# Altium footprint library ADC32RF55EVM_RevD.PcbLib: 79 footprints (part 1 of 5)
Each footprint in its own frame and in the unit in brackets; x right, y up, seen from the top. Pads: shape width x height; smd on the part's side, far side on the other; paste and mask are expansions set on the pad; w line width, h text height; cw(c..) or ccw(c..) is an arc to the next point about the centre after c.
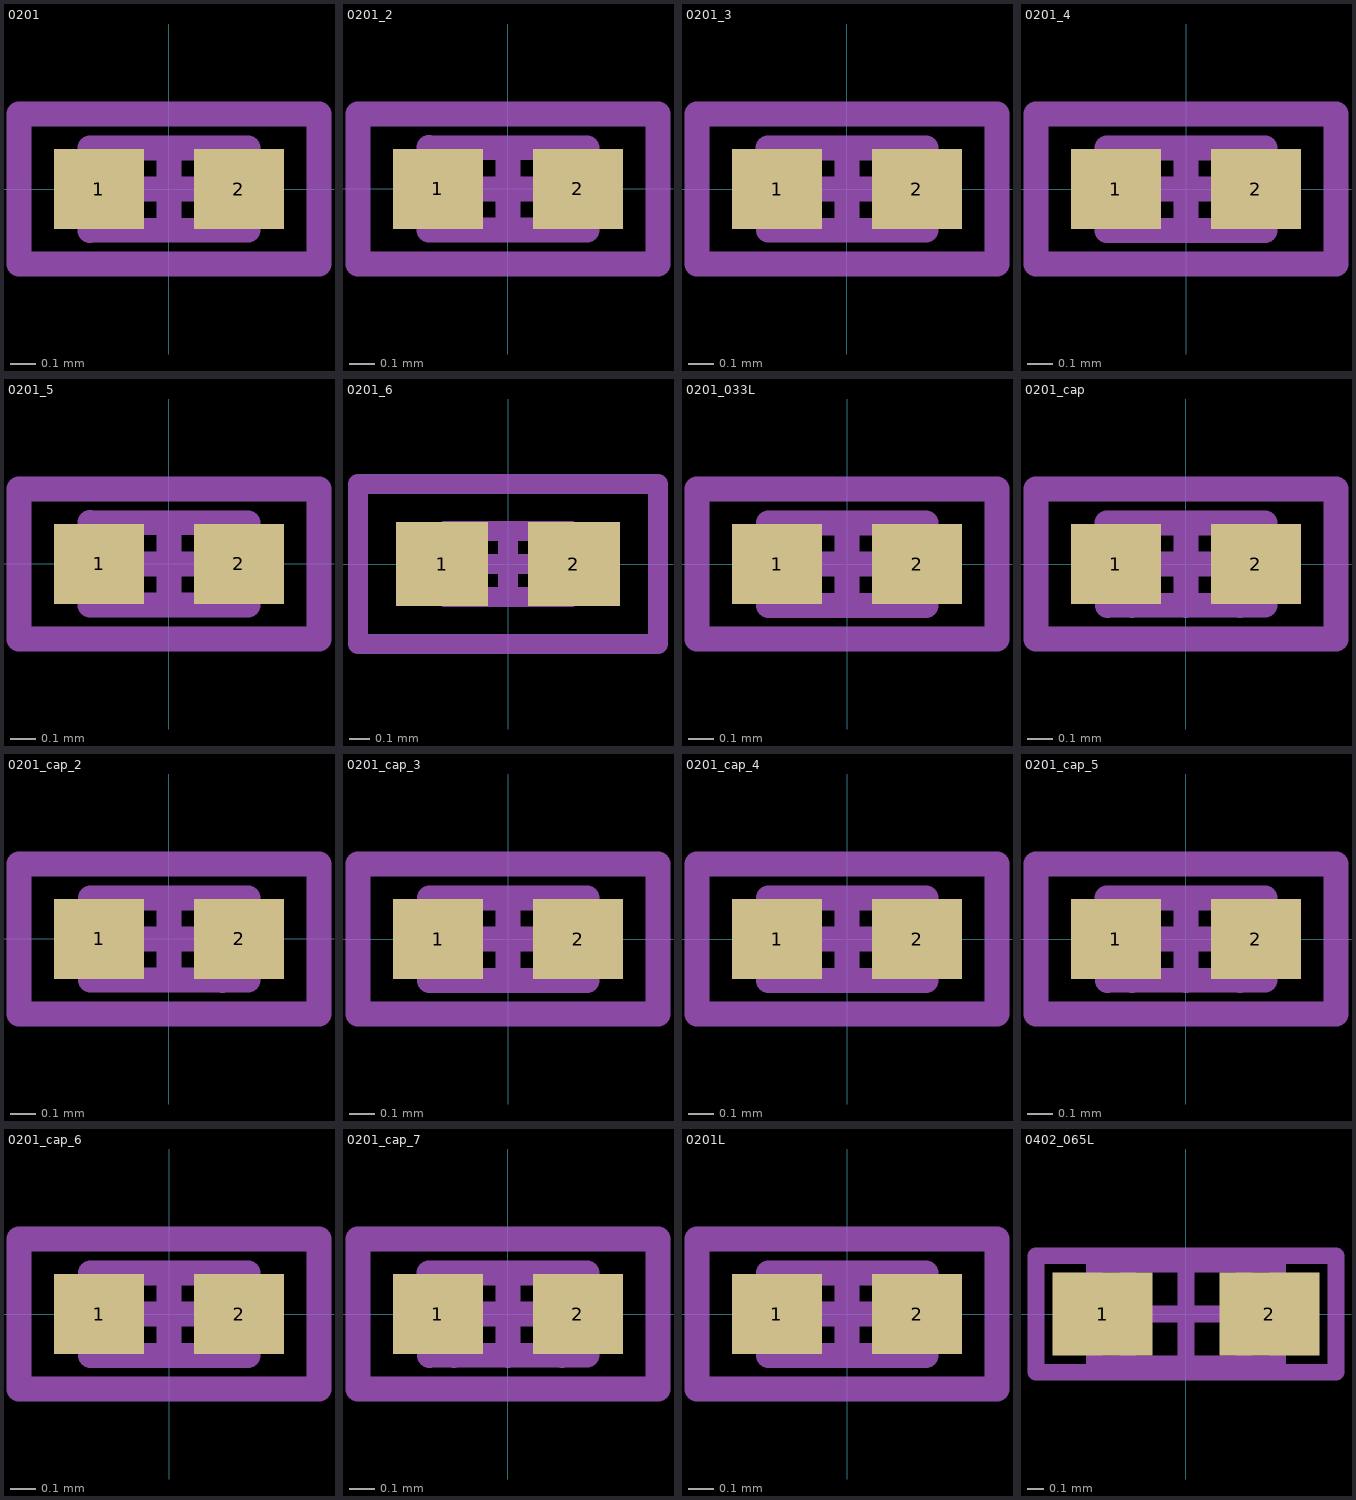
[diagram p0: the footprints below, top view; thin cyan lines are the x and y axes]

## 0201 [mm] "Data from Kemet datasheet CC101_COM dated 7/28/11"
height 0.26
pads (2):
  rect 0.36x0.32 smd mask+0.048: 1(-0.28,0) 2(0.28,0)
Mechanical 5:
  lines w0.1: -0.6,-0.3 0.6,-0.3 0.6,0.3 -0.6,0.3 -0.6,-0.3
  text ".Designator" at -0.254,0 h0.64
Mechanical 13:
  lines w0.1: -0.215,-0.165 -0.215,0.165 ; 0.215,-0.165 0.215,0.165 ; -0.315,-0.165 -0.315,0.165 0.315,0.165 0.315,-0.165 -0.315,-0.165
Mechanical 15:
  lines w0.1: -0.165,0 0.165,0 ; 0,-0.165 0,0.165 ; -0.6,-0.3 -0.6,0.3 0.6,0.3 0.6,-0.3 -0.6,-0.3
3D body: height 0.26, standoff 0, extent -0.314,-0.164 -0.216,0.164
3D body: height 0.26, standoff 0, extent -0.214,-0.164 0.214,0.164
3D body: height 0.26, standoff 0, extent 0.216,-0.164 0.315,0.164

## 0201_2 [mm]
pads (2):
  rect 0.36x0.32 smd mask+0.048: 1(-0.28,0) 2(0.28,0)
Mechanical 5:
  lines w0.1: -0.6,-0.3 -0.6,0.3 0.6,0.3 0.6,-0.3 -0.6,-0.3
  text ".Designator" at -0.254,0 h0.64
Mechanical 13:
  lines w0.1: -0.215,-0.165 -0.215,0.165 ; 0.215,-0.165 0.215,0.165 ; -0.315,-0.165 0.315,-0.165 0.315,0.165 -0.315,0.165 -0.315,-0.165
Mechanical 15:
  lines w0.1: -0.165,0 0.165,0 ; 0,-0.165 0,0.165 ; -0.6,-0.3 0.6,-0.3 0.6,0.3 -0.6,0.3 -0.6,-0.3
3D body: height 0.26, standoff 0, extent 0.216,-0.164 0.314,0.164
3D body: height 0.26, standoff 0, extent -0.214,-0.164 0.214,0.164
3D body: height 0.26, standoff 0, extent -0.314,-0.164 -0.216,0.164

## 0201_3 [mm]
pads (2):
  rect 0.36x0.32 smd mask+0.048: 1(-0.28,0) 2(0.28,0)
Mechanical 5:
  lines w0.1: -0.6,-0.3 0.6,-0.3 0.6,0.3 -0.6,0.3 -0.6,-0.3
  text ".Designator" at -0.254,0 h0.64
Mechanical 13:
  lines w0.1: -0.215,-0.165 -0.215,0.165 ; 0.215,-0.165 0.215,0.165 ; -0.315,-0.165 -0.315,0.165 0.315,0.165 0.315,-0.165 -0.315,-0.165
Mechanical 15:
  lines w0.1: -0.165,0 0.165,0 ; 0,-0.165 0,0.165 ; -0.6,-0.3 -0.6,0.3 0.6,0.3 0.6,-0.3 -0.6,-0.3
3D body: height 0.26, standoff 0, extent -0.314,-0.164 -0.216,0.164
3D body: height 0.26, standoff 0, extent -0.214,-0.164 0.214,0.164
3D body: height 0.26, standoff 0, extent 0.216,-0.164 0.314,0.164

## 0201_4 [mm]
pads (2):
  rect 0.36x0.32 smd mask+0.048: 1(-0.28,0) 2(0.28,0)
Mechanical 5:
  lines w0.1: -0.6,-0.3 0.6,-0.3 0.6,0.3 -0.6,0.3 -0.6,-0.3
  text ".Designator" at -0.254,0 h0.64
Mechanical 13:
  lines w0.1: -0.215,-0.165 -0.215,0.165 ; 0.215,-0.165 0.215,0.165 ; -0.315,-0.165 -0.315,0.165 0.315,0.165 0.315,-0.165 -0.315,-0.165
Mechanical 15:
  lines w0.1: -0.165,0 0.165,0 ; 0,-0.165 0,0.165 ; -0.6,-0.3 -0.6,0.3 0.6,0.3 0.6,-0.3 -0.6,-0.3
3D body: height 0.26, standoff 0, extent -0.314,-0.164 -0.216,0.164
3D body: height 0.26, standoff 0, extent -0.214,-0.164 0.214,0.164
3D body: height 0.26, standoff 0, extent 0.216,-0.164 0.314,0.164

## 0201_5 [mm]
pads (2):
  rect 0.36x0.32 smd mask+0.048: 1(-0.28,0) 2(0.28,0)
Mechanical 5:
  lines w0.1: -0.6,-0.3 0.6,-0.3 0.6,0.3 -0.6,0.3 -0.6,-0.3
  text ".Designator" at -0.254,0 h0.64
Mechanical 13:
  lines w0.1: -0.215,-0.165 -0.215,0.165 ; 0.215,-0.165 0.215,0.165 ; -0.315,-0.165 -0.315,0.165 0.315,0.165 0.315,-0.165 -0.315,-0.165
Mechanical 15:
  lines w0.1: -0.165,0 0.165,0 ; 0,-0.165 0,0.165 ; -0.6,-0.3 -0.6,0.3 0.6,0.3 0.6,-0.3 -0.6,-0.3
3D body: height 0.26, standoff 0, extent -0.314,-0.164 -0.216,0.164
3D body: height 0.26, standoff 0, extent -0.214,-0.164 0.214,0.164
3D body: height 0.26, standoff 0, extent 0.216,-0.164 0.314,0.164

## 0201_6 [mm]
pads (2):
  rect 0.46x0.42 smd mask+0.048: 1(-0.33,0) 2(0.33,0)
Mechanical 5:
  lines w0.1: -0.75,-0.4 0.75,-0.4 0.75,0.4 -0.75,0.4 -0.75,-0.4
  text ".Designator" at -0.66,-0.178 h0.36
Mechanical 13:
  lines w0.1: -0.215,-0.165 -0.215,0.165 ; 0.215,-0.165 0.215,0.165 ; -0.315,-0.165 -0.315,0.165 0.315,0.165 0.315,-0.165 -0.315,-0.165
Mechanical 15:
  lines w0.1: -0.165,0 0.165,0 ; 0,-0.165 0,0.165 ; -0.75,-0.4 -0.75,0.4 0.75,0.4 0.75,-0.4 -0.75,-0.4
3D body: height 0.26, standoff 0, extent -0.314,-0.164 -0.216,0.164
3D body: height 0.26, standoff 0, extent -0.214,-0.164 0.214,0.164
3D body: height 0.26, standoff 0, extent 0.216,-0.164 0.314,0.164

## 0201_033L [mm] "0201"
height 0.33
pads (2):
  rect 0.36x0.32 smd mask+0.048: 1(-0.28,0) 2(0.28,0)
Mechanical 5:
  lines w0.1: -0.6,-0.3 -0.6,0.3 0.6,0.3 0.6,-0.3 -0.6,-0.3
  text ".Designator" at -0.5,-0.15 h0.28
Mechanical 13:
  lines w0.1: -0.215,-0.165 -0.215,0.165 ; 0.215,-0.165 0.215,0.165 ; -0.315,-0.165 0.315,-0.165 0.315,0.165 -0.315,0.165 -0.315,-0.165
Mechanical 15:
  lines w0.1: -0.165,0 0.165,0 ; 0,-0.165 0,0.165 ; -0.6,-0.3 0.6,-0.3 0.6,0.3 -0.6,0.3 -0.6,-0.3
3D body: height 0.33, standoff 0, extent 0.216,-0.164 0.314,0.164
3D body: height 0.33, standoff 0, extent -0.214,-0.164 0.214,0.164
3D body: height 0.33, standoff 0, extent -0.314,-0.164 -0.216,0.164

## 0201_cap [mm] "Data from Kemet datasheet CC101_COM dated 7/28/11"
height 0.26
pads (2):
  rect 0.36x0.32 smd mask+0.048: 1(-0.28,0) 2(0.28,0)
Mechanical 5:
  lines w0.1: -0.6,-0.3 -0.6,0.3 0.6,0.3 0.6,-0.3 -0.6,-0.3
  text ".Designator" at -0.254,0 h0.64
Mechanical 13:
  lines w0.1: -0.215,-0.165 -0.215,0.165 ; 0.215,-0.165 0.215,0.165 ; -0.315,-0.165 0.315,-0.165 0.315,0.165 -0.315,0.165 -0.315,-0.165
Mechanical 15:
  lines w0.1: -0.165,0 0.165,0 ; 0,-0.165 0,0.165 ; -0.6,-0.3 0.6,-0.3 0.6,0.3 -0.6,0.3 -0.6,-0.3
3D body: height 0.26, standoff 0, extent 0.216,-0.164 0.314,0.164
3D body: height 0.26, standoff 0, extent -0.314,-0.164 -0.216,0.164
3D body: height 0.26, standoff 0, extent -0.214,-0.164 0.214,0.164

## 0201_cap_2 [mm]
pads (2):
  rect 0.36x0.32 smd mask+0.048: 1(-0.28,0) 2(0.28,0)
Mechanical 5:
  lines w0.1: -0.6,-0.3 0.6,-0.3 0.6,0.3 -0.6,0.3 -0.6,-0.3
  text ".Designator" at -0.254,0 h0.64
Mechanical 13:
  lines w0.1: -0.215,-0.165 -0.215,0.165 ; 0.215,-0.165 0.215,0.165 ; -0.315,-0.165 -0.315,0.165 0.315,0.165 0.315,-0.165 -0.315,-0.165
Mechanical 15:
  lines w0.1: -0.165,0 0.165,0 ; 0,-0.165 0,0.165 ; -0.6,-0.3 -0.6,0.3 0.6,0.3 0.6,-0.3 -0.6,-0.3
3D body: height 0.26, standoff 0, extent -0.214,-0.164 0.214,0.164
3D body: height 0.26, standoff 0, extent -0.314,-0.164 -0.216,0.164
3D body: height 0.26, standoff 0, extent 0.216,-0.164 0.314,0.164

## 0201_cap_3 [mm]
pads (2):
  rect 0.36x0.32 smd mask+0.048: 1(-0.28,0) 2(0.28,0)
Mechanical 5:
  lines w0.1: -0.6,-0.3 0.6,-0.3 0.6,0.3 -0.6,0.3 -0.6,-0.3
  text ".Designator" at -0.254,0 h0.64
Mechanical 13:
  lines w0.1: -0.215,-0.165 -0.215,0.165 ; 0.215,-0.165 0.215,0.165 ; -0.315,-0.165 -0.315,0.165 0.315,0.165 0.315,-0.165 -0.315,-0.165
Mechanical 15:
  lines w0.1: -0.165,0 0.165,0 ; 0,-0.165 0,0.165 ; -0.6,-0.3 -0.6,0.3 0.6,0.3 0.6,-0.3 -0.6,-0.3
3D body: height 0.26, standoff 0, extent -0.214,-0.164 0.214,0.164
3D body: height 0.26, standoff 0, extent -0.314,-0.164 -0.216,0.164
3D body: height 0.26, standoff 0, extent 0.216,-0.164 0.314,0.164

## 0201_cap_4 [mm]
pads (2):
  rect 0.36x0.32 smd mask+0.048: 1(-0.28,0) 2(0.28,0)
Mechanical 5:
  lines w0.1: -0.6,-0.3 0.6,-0.3 0.6,0.3 -0.6,0.3 -0.6,-0.3
  text ".Designator" at -0.254,0 h0.64
Mechanical 13:
  lines w0.1: -0.215,-0.165 -0.215,0.165 ; 0.215,-0.165 0.215,0.165 ; -0.315,-0.165 -0.315,0.165 0.315,0.165 0.315,-0.165 -0.315,-0.165
Mechanical 15:
  lines w0.1: -0.165,0 0.165,0 ; 0,-0.165 0,0.165 ; -0.6,-0.3 -0.6,0.3 0.6,0.3 0.6,-0.3 -0.6,-0.3
3D body: height 0.26, standoff 0, extent -0.214,-0.164 0.214,0.164
3D body: height 0.26, standoff 0, extent -0.314,-0.164 -0.216,0.164
3D body: height 0.26, standoff 0, extent 0.216,-0.164 0.314,0.164

## 0201_cap_5 [mm]
pads (2):
  rect 0.36x0.32 smd mask+0.048: 1(-0.28,0) 2(0.28,0)
Mechanical 5:
  lines w0.1: -0.6,-0.3 0.6,-0.3 0.6,0.3 -0.6,0.3 -0.6,-0.3
  text ".Designator" at -0.254,0 h0.64
Mechanical 13:
  lines w0.1: -0.215,-0.165 -0.215,0.165 ; 0.215,-0.165 0.215,0.165 ; -0.315,-0.165 -0.315,0.165 0.315,0.165 0.315,-0.165 -0.315,-0.165
Mechanical 15:
  lines w0.1: -0.165,0 0.165,0 ; 0,-0.165 0,0.165 ; -0.6,-0.3 -0.6,0.3 0.6,0.3 0.6,-0.3 -0.6,-0.3
3D body: height 0.26, standoff 0, extent -0.214,-0.164 0.214,0.164
3D body: height 0.26, standoff 0, extent -0.314,-0.164 -0.216,0.164
3D body: height 0.26, standoff 0, extent 0.216,-0.164 0.314,0.164

## 0201_cap_6 [mm]
pads (2):
  rect 0.36x0.32 smd mask+0.048: 1(-0.28,0) 2(0.28,0)
Mechanical 5:
  lines w0.1: -0.6,-0.3 -0.6,0.3 0.6,0.3 0.6,-0.3 -0.6,-0.3
  text ".Designator" at -0.254,0 h0.64
Mechanical 13:
  lines w0.1: -0.215,-0.165 -0.215,0.165 ; 0.215,-0.165 0.215,0.165 ; -0.315,-0.165 0.315,-0.165 0.315,0.165 -0.315,0.165 -0.315,-0.165
Mechanical 15:
  lines w0.1: -0.165,0 0.165,0 ; 0,-0.165 0,0.165 ; -0.6,-0.3 0.6,-0.3 0.6,0.3 -0.6,0.3 -0.6,-0.3
3D body: height 0.26, standoff 0, extent 0.216,-0.164 0.314,0.164
3D body: height 0.26, standoff 0, extent -0.314,-0.164 -0.216,0.164
3D body: height 0.26, standoff 0, extent -0.214,-0.164 0.214,0.164

## 0201_cap_7 [mm]
pads (2):
  rect 0.36x0.32 smd mask+0.048: 1(-0.28,0) 2(0.28,0)
Mechanical 5:
  lines w0.1: -0.6,-0.3 -0.6,0.3 0.6,0.3 0.6,-0.3 -0.6,-0.3
  text ".Designator" at -0.254,0 h0.64
Mechanical 13:
  lines w0.1: -0.215,-0.165 -0.215,0.165 ; 0.215,-0.165 0.215,0.165 ; -0.315,-0.165 0.315,-0.165 0.315,0.165 -0.315,0.165 -0.315,-0.165
Mechanical 15:
  lines w0.1: -0.165,0 0.165,0 ; 0,-0.165 0,0.165 ; -0.6,-0.3 0.6,-0.3 0.6,0.3 -0.6,0.3 -0.6,-0.3
3D body: height 0.26, standoff 0, extent 0.216,-0.164 0.314,0.164
3D body: height 0.26, standoff 0, extent -0.314,-0.164 -0.216,0.164
3D body: height 0.26, standoff 0, extent -0.214,-0.164 0.214,0.164

## 0201L [mm] "Data from Kemet datasheet CC101_COM dated 7/28/11"
height 0.26
pads (2):
  rect 0.36x0.32 smd mask+0.048: 1(-0.28,0) 2(0.28,0)
Mechanical 5:
  lines w0.1: -0.6,-0.3 -0.6,0.3 0.6,0.3 0.6,-0.3 -0.6,-0.3
  text ".Designator" at -0.5,-0.15 h0.28
Mechanical 13:
  lines w0.1: -0.215,-0.165 -0.215,0.165 ; 0.215,-0.165 0.215,0.165 ; -0.315,-0.165 0.315,-0.165 0.315,0.165 -0.315,0.165 -0.315,-0.165
Mechanical 15:
  lines w0.1: -0.165,0 0.165,0 ; 0,-0.165 0,0.165 ; -0.6,-0.3 0.6,-0.3 0.6,0.3 -0.6,0.3 -0.6,-0.3
3D body: height 0.26, standoff 0, extent 0.216,-0.164 0.314,0.164
3D body: height 0.26, standoff 0, extent -0.214,-0.164 0.214,0.164
3D body: height 0.26, standoff 0, extent -0.314,-0.164 -0.216,0.164

## 0402_065L [mm] "0402"
height 0.65
pads (2):
  rect 0.6x0.5 smd: 1(-0.5,0) 2(0.5,0)
Mechanical 5:
  lines w0.1: -0.9,-0.35 0.9,-0.35 0.9,0.35 -0.9,0.35 -0.9,-0.35
  text ".Designator" at -0.775,-0.225 h0.43
Mechanical 13:
  lines w0.1: -0.35,-0.3 -0.35,0.3 ; 0.35,-0.3 0.35,0.3 ; -0.55,-0.3 -0.55,0.3 0.55,0.3 0.55,-0.3 -0.55,-0.3
Mechanical 15:
  lines w0.1: -0.3,0 0.3,0 ; 0,-0.3 0,0.3 ; -0.9,-0.35 -0.9,0.35 0.9,0.35 0.9,-0.35 -0.9,-0.35
3D body: height 0.65, standoff 0, extent -0.549,-0.299 -0.351,0.299
3D body: height 0.65, standoff 0, extent -0.349,-0.299 0.349,0.299
3D body: height 0.65, standoff 0, extent 0.351,-0.299 0.549,0.299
